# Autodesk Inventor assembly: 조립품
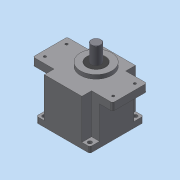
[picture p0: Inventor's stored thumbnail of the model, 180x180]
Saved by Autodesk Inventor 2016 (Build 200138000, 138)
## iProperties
Created: 2020-08
Part Number: 조립품
Material: 일반
Document SubType Name: Assembly
Designer: User
Author: User
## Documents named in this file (10)
- C:\Users\User\Desktop\700815V1001\조립품.iam
- C:\Users\User\Desktop\700815V1001\메인 축.ipt
- C:\Users\User\Desktop\700815V1001\베어링 608.ipt
- C:\Users\User\Desktop\700815V1001\베어링 6003.ipt
- C:\Users\User\Desktop\700815V1001\본체.ipt
- C:\Users\User\Desktop\700815V1001\볼트 M4.ipt
- C:\Users\User\Desktop\700815V1001\서브 축.ipt
- C:\Users\User\Desktop\700815V1001\오일 실 8 22 7.ipt
- C:\Users\User\Desktop\700815V1001\오일 실 17 32 8.ipt
- C:\Users\User\Desktop\700815V1001\커버.ipt
